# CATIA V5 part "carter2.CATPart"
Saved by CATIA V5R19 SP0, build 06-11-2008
Part number: carter2
Bounding box of the stored display mesh (mm): x -64.982 to 64.982, y -75 to 125, z -64.915 to 64.915
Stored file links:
  F:\20\carter2.CATPart
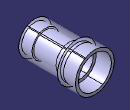
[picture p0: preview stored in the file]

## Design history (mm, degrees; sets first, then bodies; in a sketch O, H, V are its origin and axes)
Set1
  Point1: type Center, Curve edge [face of Shaft1 from Sketch1.L9 | face of Shaft1 from Sketch1.L8]
  Line1: type Normal, RefSkin face of Shaft1 from Sketch1.L9, Start 0, End 20, RefPoint Point1
Body1 (main body)
  Sketch1 on yz-plane, origin (0, 0, 0), H (0, 1, 0), V (0, 0, 1)
    line L1 (-75, 55) -> (-75, 45)
    line L2 (-75, 45) -> (-40, 45)
    line L3 (-40, 45) -> (-40, 40)
    line L4 (-40, 40) -> (40, 40)
    line L5 (40, 40) -> (40, 45)
    point P6 (40, 45)
    line L6 (40, 45) -> (75, 45)
    line L7 (75, 45) -> (75, 55)
    line L8 (75, 55) -> (125, 55)
    line L9 (125, 55) -> (125, 65)
    line L10 (125, 65) -> (65, 65)
    line L11 (65, 65) -> (65, 55)
    line L12 (65, 55) -> (-75, 55)
    distance L12 L2 = 10
    distance L12 L4 = 15
    distance L8 L10 = 10
    distance L11 L7 = 10
    length L6 = 35
    length L2 = 35
    length L4 = 80
    distance L8 L6 = 10
    length L10 = 60
    distance L4 H = 40
    vertical: L1 V, L3 V, L5 V, L7 V, L9 V, L11 V
    horizontal: L2 H, L4 H, L6 H, L8 H, L10 H
    coincidence: P6 L2
    symmetry: L3 L5 V
  Shaft1: profile Sketch1, axis Sketch1.H, angle 360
